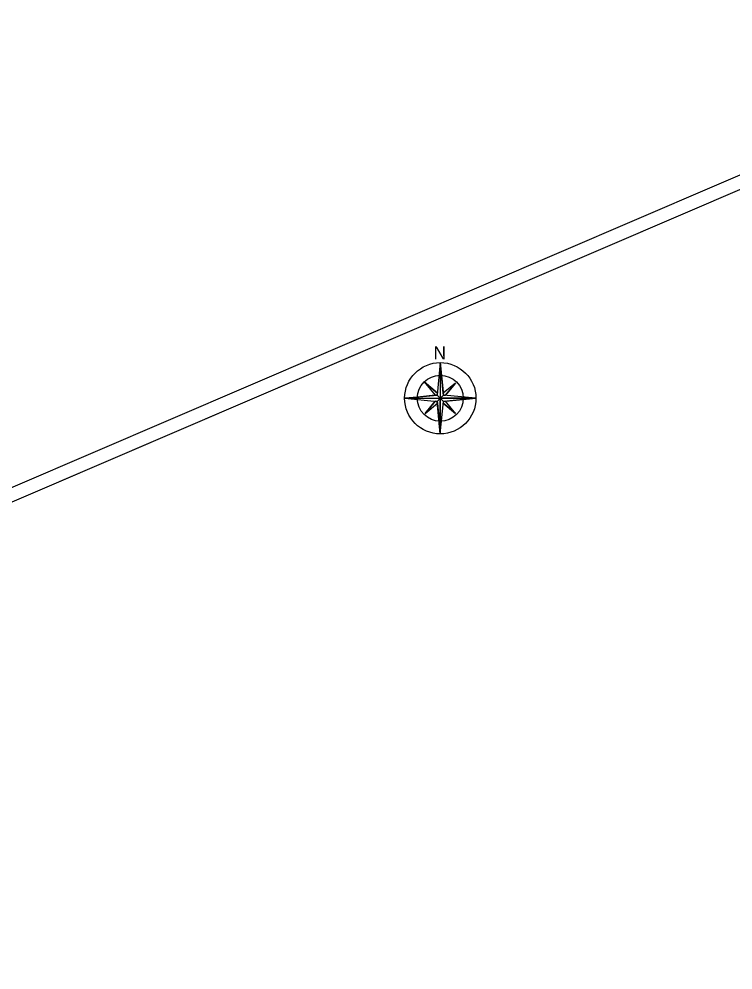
# Model space of a CAD drawing. Extents: x 7500108 to 7500715, y 5768804 to 5769157.
# Drawn here: x 7500411.6 to 7500544.2, y 5768980.6 to 5769157.1 of the extents above; entities that cross this region are included whole.
import ezdxf

# ---------------------------------------------------------------- set-up
doc = ezdxf.new("R2010")
doc.units = 0
for name, color, linetype in [('1_proj_KD_etap3', 7, 'Continuous'), ('_Roża Wiatrów', 7, 'Continuous'), ('CMENTARZE_I_POMNIKI', 7, 'Continuous'), ('DZIALKI', 7, 'Continuous')]:
    doc.layers.add(name, color=color, linetype=linetype)

msp = doc.modelspace()

# ---------------------------------------------------------------- linework, layer by layer
at = {"layer": '1_proj_KD_etap3'}
msp.add_lwpolyline([(7500603.81, 5768994.34), (7500172.11, 5768809.11), (7500115.53, 5768940.99), (7500547.22, 5769126.21)], close=True, dxfattribs=at)
at = {"layer": '_Roża Wiatrów'}
for p, q in [((7500489.84, 5769093.32), (7500489.26, 5769087.28)), ((7500489.84, 5769093.32), (7500489.84, 5769080.08)), ((7500489.84, 5769093.32), (7500490.42, 5769087.28)), ((7500486.83, 5769089.72), (7500488.89, 5769087.25)), ((7500486.83, 5769089.72), (7500489.3, 5769087.65)), ((7500492.65, 5769089.51), (7500490.39, 5769087.64)), ((7500492.65, 5769089.51), (7500490.79, 5769087.25)), ((7500483.23, 5769086.7), (7500489.26, 5769087.28)), ((7500489.26, 5769087.28), (7500489.84, 5769086.7)), ((7500490.42, 5769087.28), (7500489.84, 5769086.7)), ((7500496.46, 5769086.7), (7500490.42, 5769087.28)), ((7500483.23, 5769086.7), (7500496.46, 5769086.7)), ((7500483.23, 5769086.7), (7500489.26, 5769086.12)), ((7500487.04, 5769083.89), (7500488.9, 5769086.16)), ((7500487.04, 5769083.89), (7500489.3, 5769085.76)), ((7500489.26, 5769086.12), (7500489.84, 5769086.7)), ((7500489.84, 5769080.08), (7500489.26, 5769086.12)), ((7500490.42, 5769086.12), (7500489.84, 5769086.7)), ((7500489.84, 5769080.08), (7500490.42, 5769086.12)), ((7500492.65, 5769083.89), (7500490.39, 5769085.76)), ((7500496.46, 5769086.7), (7500490.42, 5769086.12)), ((7500492.65, 5769083.89), (7500490.79, 5769086.16))]:
    msp.add_line(p, q, dxfattribs=at)
for points in [[(7500490.07, 5769090.96), (7500489.84, 5769093.32), (7500489.84, 5769090.97)], [(7500489.84, 5769090.97), (7500489.84, 5769086.7), (7500490.42, 5769087.28), (7500490.39, 5769087.64), (7500490.07, 5769090.96)], [(7500488.89, 5769087.25), (7500489.26, 5769087.28), (7500489.3, 5769087.65), (7500486.83, 5769089.72), (7500488.89, 5769087.25)], [(7500490.39, 5769087.64), (7500490.42, 5769087.28), (7500490.79, 5769087.25), (7500492.65, 5769089.51), (7500490.39, 5769087.64)], [(7500485.58, 5769086.7), (7500489.84, 5769086.7), (7500489.26, 5769087.28), (7500488.89, 5769087.25), (7500485.58, 5769086.93)], [(7500485.58, 5769086.93), (7500483.23, 5769086.7), (7500485.58, 5769086.7)], [(7500489.3, 5769085.76), (7500489.26, 5769086.12), (7500488.9, 5769086.16), (7500487.04, 5769083.89), (7500489.3, 5769085.76)], [(7500489.84, 5769082.43), (7500489.84, 5769086.7), (7500489.26, 5769086.12), (7500489.3, 5769085.76), (7500489.62, 5769082.44)], [(7500494.11, 5769086.7), (7500489.84, 5769086.7), (7500490.42, 5769086.12), (7500490.79, 5769086.16), (7500494.11, 5769086.47)], [(7500490.79, 5769086.16), (7500490.42, 5769086.12), (7500490.39, 5769085.76), (7500492.65, 5769083.89), (7500490.79, 5769086.16)], [(7500494.11, 5769086.47), (7500496.46, 5769086.7), (7500494.11, 5769086.7)], [(7500489.62, 5769082.44), (7500489.84, 5769080.08), (7500489.84, 5769082.43)]]:
    msp.add_lwpolyline(points, dxfattribs=at)
for radius in [6.62, 4.27]:
    msp.add_circle((7500489.84, 5769086.7), radius, dxfattribs=at)
for start, end in [(86.9566, 90), (86.9566, 90), (176.9566, 180), (176.9566, 180), (356.9566, 360), (356.9566, 360), (266.9566, 270), (266.9566, 270)]:
    msp.add_arc((7500489.84, 5769086.7), 4.27, start, end, dxfattribs=at)
at = {"layer": 'CMENTARZE_I_POMNIKI'}
msp.add_lwpolyline([(7500144.97, 5768872.37), (7500115.53, 5768940.99), (7500547.22, 5769126.21), (7500566.93, 5769080.29), (7500577.05, 5769056.69), (7500603.81, 5768994.34), (7500172.11, 5768809.11), (7500169.25, 5768815.79)], close=True, dxfattribs=at)
at = {"layer": 'DZIALKI'}
for points in [[(7500108.06, 5768940.5), (7500612.86, 5769157.1), (7500671.42, 5769020.63), (7500166.62, 5768804.03)], [(7500115.01, 5768940.77), (7500547.22, 5769126.21), (7500550.88, 5769117.68), (7500586.52, 5769034.61), (7500603.81, 5768994.34), (7500171.6, 5768808.89)]]:
    msp.add_lwpolyline(points, close=True, dxfattribs=at)

# ---------------------------------------------------------------- texts
at = {"layer": '_Roża Wiatrów'}
msp.add_text('N', height=2.4, rotation=360, dxfattribs=at).set_placement((7500488.58, 5769093.95))

doc.saveas('drawing.dxf')
